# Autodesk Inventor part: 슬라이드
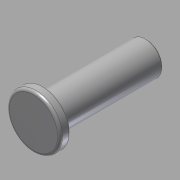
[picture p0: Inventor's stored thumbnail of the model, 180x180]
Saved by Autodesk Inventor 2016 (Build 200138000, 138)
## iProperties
Company: 한국ATC센터
Created: 2015-11
Part Number: 슬라이드
Document SubType Name: Modeling
Designer: mdu
Density: 7.86 g/cm^3
Material: 강철, 연강
Mass: 53.476 g
Surface Area: 25.6477 cm^2
Volume: 6.80356 cm^3
Appearance: 강철
Author: mdu
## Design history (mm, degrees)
sketch "스케치1"
  geometry: L1 (13.5, 41)-(13.5, 74) reference; L2 (13.5, 74)-(26.5, 74) reference; L3 (20, 74)-(20, 29); L4 (20, 74)-(13.5, 74); L5 (13.5, 74)-(13.5, 33); L6 (13.5, 33)-(9.5, 33); L7 (9.5, 33)-(9.5, 29); L8 (20, 73.5)-(13.5, 73.5); L9 (20, 29)-(9.5, 29); 1 further point
  constraints: 16 end point, 4 perpendicular, 3 point on line, 1 collinear, 1 midpoint, 1 parallel, 1 vertical, 2 other
  dimensions: "d0" = 45 distance of L3.start L3.end; "d1" = 21 diameter of L7 L3; "d2" = 4 distance from line of L3.end L6; "d4" = 0.5 distance between parallel lines of L8 L2
revolve "회전1" sketch "스케치1" stored, may be unused: angle "d5" = 90 deg
fillet "모깎기1" dims "d6" = 1
fillet "모깎기3" dims "d8" = 0.5
chamfer "모따기1" distance "d9" = 0.5; stored, may be unused: second distance "d10" = 2, angle "d11" = 45 deg
sketch "스케치2"
  geometry: C1 r 6.5 at (0, 0) reference; C2 r 7.25 at (0, 0); 1 further point
  constraints: 1 centre point, 1 coincident
  dimensions: "d12" = 14.5 diameter of C2
extrude "돌출1" join sketch "스케치2" distance "d13" = 2; taper "d14" = 0 deg
node "솔리드1"
node "참조1"
